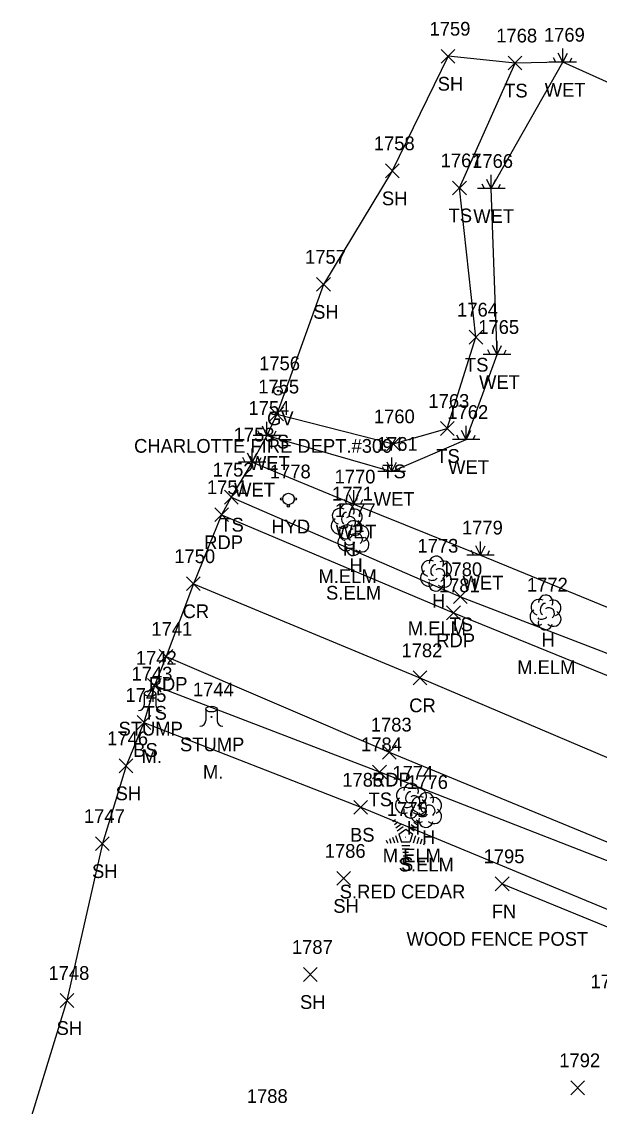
# Model space of a CAD drawing. Extents: x 1459992 to 1461532, y 647785 to 648535.
# Drawn here: x 1460921.8 to 1461005.9, y 648288.6 to 648446.3 of the extents above; entities that cross this region are included whole.
import ezdxf

# ---------------------------------------------------------------- set-up
doc = ezdxf.new("R2010")
doc.units = 0
for name, color, linetype in [('L_A', 7, 'Continuous'), ('L_C', 7, 'Continuous'), ('L_I', 7, 'Continuous'), ('L_TIC', 7, 'Continuous'), ('LELB', 7, 'Continuous'), ('LFNC', 7, 'Continuous'), ('LSOGP', 7, 'Continuous'), ('LTC', 7, 'Continuous'), ('LTD', 7, 'Continuous'), ('LTS', 7, 'Continuous'), ('LWET', 7, 'Continuous'), ('P_A', 7, 'Continuous'), ('P_I', 7, 'Continuous'), ('P_TIC', 7, 'Continuous'), ('PET', 7, 'Continuous'), ('PRC', 7, 'Continuous'), ('U_A', 7, 'Continuous'), ('U_C', 7, 'Continuous'), ('U_I', 7, 'Continuous'), ('UWFH', 7, 'Continuous'), ('UWV', 7, 'Continuous')]:
    doc.layers.add(name, color=color, linetype=linetype)

msp = doc.modelspace()

# ---------------------------------------------------------------- linework, layer by layer
at = {"layer": 'L_TIC'}
for points in [[(1460982.9, 648440.23), (1460984.9, 648442.23)], [(1460984.9, 648440.23), (1460982.9, 648442.23)], [(1460992.65, 648439.24), (1460994.65, 648441.24)], [(1460994.65, 648439.24), (1460992.65, 648441.24)], [(1460974.78, 648423.57), (1460976.78, 648425.57)], [(1460976.78, 648423.57), (1460974.78, 648425.57)], [(1460984.56, 648421.09), (1460986.56, 648423.09)], [(1460986.56, 648421.09), (1460984.56, 648423.09)], [(1460964.77, 648407.07), (1460966.77, 648409.07)], [(1460966.77, 648407.07), (1460964.77, 648409.07)], [(1460986.95, 648399.39), (1460988.95, 648401.39)], [(1460988.95, 648399.39), (1460986.95, 648401.39)], [(1460957.96, 648388.21), (1460959.96, 648390.21)], [(1460959.96, 648388.21), (1460957.96, 648390.21)], [(1460982.78, 648386.12), (1460984.78, 648388.12)], [(1460984.78, 648386.12), (1460982.78, 648388.12)], [(1460974.92, 648383.88), (1460976.92, 648385.88)], [(1460976.92, 648383.88), (1460974.92, 648385.88)], [(1460951.34, 648376.13), (1460953.34, 648378.13)], [(1460953.34, 648376.13), (1460951.34, 648378.13)], [(1460984.69, 648361.66), (1460986.69, 648363.66)], [(1460986.69, 648361.66), (1460984.69, 648363.66)], [(1460940.15, 648348.78), (1460942.15, 648350.78)], [(1460942.15, 648348.78), (1460940.15, 648350.78)], [(1460938.64, 648343.38), (1460940.64, 648345.38)], [(1460940.64, 648343.38), (1460938.64, 648345.38)], [(1460936.03, 648337.08), (1460938.03, 648339.08)], [(1460938.03, 648337.08), (1460936.03, 648339.08)], [(1460972.92, 648336.2), (1460974.92, 648338.2)], [(1460974.92, 648336.2), (1460972.92, 648338.2)], [(1460970.19, 648331.05), (1460972.19, 648333.05)], [(1460972.19, 648331.05), (1460970.19, 648333.05)], [(1460932.59, 648325.77), (1460934.59, 648327.77)], [(1460934.59, 648325.77), (1460932.59, 648327.77)], [(1460967.7, 648320.71), (1460969.7, 648322.71)], [(1460969.7, 648320.71), (1460967.7, 648322.71)], [(1460990.77, 648319.92), (1460992.77, 648321.92)], [(1460992.77, 648319.92), (1460990.77, 648321.92)], [(1460962.86, 648306.74), (1460964.86, 648308.74)], [(1460964.86, 648306.74), (1460962.86, 648308.74)], [(1460927.43, 648302.96), (1460929.43, 648304.96)], [(1460929.43, 648302.96), (1460927.43, 648304.96)], [(1461001.77, 648290.27), (1461003.77, 648292.27)], [(1461003.77, 648290.27), (1461001.77, 648292.27)]]:
    msp.add_lwpolyline(points, dxfattribs=at)
at = {"layer": 'LELB'}
for points in [[(1460952.34, 648377.13), (1460985.69, 648362.66), (1461027.43, 648346.63), (1461054.39, 648335.28), (1461097.58, 648319.81), (1461127.3, 648308.18), (1461153.51, 648301.33), (1461179.78, 648297.83), (1461204.84, 648300.47), (1461233.15, 648308.09), (1461257.01, 648318.59), (1461281.51, 648336.52), (1461300.79, 648352.57), (1461310.07, 648360.68), (1461331.77, 648379.2), (1461352.47, 648399.38), (1461367.35, 648413.21), (1461394.44, 648433.89), (1461417.38, 648445.8)], [(1460958.96, 648389.21), (1460975.92, 648384.88), (1460983.78, 648387.12), (1460987.95, 648400.39), (1460985.56, 648422.09), (1460993.65, 648440.24)], [(1460941.15, 648349.78), (1460973.92, 648337.2), (1461015.24, 648321.11), (1461040.67, 648310.01), (1461064.18, 648298.16), (1461082.22, 648291.36), (1461125.02, 648274.34), (1461150.75, 648265.39), (1461172.28, 648256.95), (1461198.57, 648246.42), (1461223, 648236.28), (1461241.79, 648231.37), (1461257.62, 648226.89), (1461266.9, 648221.63), (1461276.01, 648214.68), (1461281.47, 648211.06), (1461286.34, 648210.46)], [(1460939.64, 648344.38), (1460971.19, 648332.05), (1461013, 648314.77), (1461039.31, 648304.76), (1461062.9, 648294.47), (1461067.87, 648294.36), (1461073.92, 648287.11), (1461122.33, 648270.19), (1461146.57, 648259.51), (1461168.44, 648252.02), (1461196.41, 648241.56), (1461220.18, 648231.28), (1461239.03, 648226.47), (1461251, 648216.36), (1461259.3, 648208.22), (1461262.9, 648204.94)]]:
    msp.add_lwpolyline(points, dxfattribs=at)
at = {"layer": 'LFNC'}
msp.add_lwpolyline([(1460991.77, 648320.92), (1461037.89, 648302.09), (1461026.11, 648281.23)], dxfattribs=at)
at = {"layer": 'LSOGP'}
msp.add_lwpolyline([(1461138.91, 648400.04), (1461102.42, 648405.45), (1461097.92, 648407.66), (1461049.42, 648422.26), (1461028.66, 648427.76), (1461000.6, 648440.35), (1460993.65, 648440.24), (1460983.9, 648441.23), (1460975.78, 648424.57), (1460965.77, 648408.07), (1460958.96, 648389.21), (1460957.54, 648386.1), (1460955.38, 648382.22), (1460952.34, 648377.13), (1460950.93, 648374.58), (1460946.83, 648364.55), (1460942.85, 648353.98), (1460941.15, 648349.78), (1460940.52, 648347.48), (1460939.64, 648344.38), (1460937.03, 648338.08), (1460933.59, 648326.77), (1460928.43, 648303.96), (1460921.84, 648282.44)], dxfattribs=at)
at = {"layer": 'LTC'}
for p, q in [((1460975.87, 648330.01), (1460976.23, 648330.27)), ((1460976.08, 648329.55), (1460976.61, 648329.93)), ((1460976.29, 648329.08), (1460977, 648329.59)), ((1460978.53, 648329.55), (1460979.21, 648329.06)), ((1460978.9, 648329.9), (1460979.45, 648329.5)), ((1460979.27, 648330.25), (1460979.69, 648329.95)), ((1460976.27, 648327.94), (1460976.6, 648326.92)), ((1460976.5, 648328.61), (1460977.38, 648329.25)), ((1460976.73, 648328.16), (1460977.74, 648328.89)), ((1460976.73, 648328.16), (1460977.11, 648326.97)), ((1460977.74, 648328.89), (1460978.74, 648328.17)), ((1460978.16, 648329.21), (1460978.97, 648328.62)), ((1460978.74, 648328.17), (1460978.34, 648326.97)), ((1460979.17, 648327.9), (1460978.84, 648326.86)), ((1460974.91, 648327.29), (1460975.06, 648326.82)), ((1460975.36, 648327.51), (1460975.57, 648326.85)), ((1460975.82, 648327.72), (1460976.09, 648326.89)), ((1460978.34, 648326.97), (1460977.11, 648326.97)), ((1460978.31, 648326.47), (1460977.16, 648326.47)), ((1460979.62, 648327.65), (1460979.33, 648326.76)), ((1460980.06, 648327.4), (1460979.83, 648326.67)), ((1460980.51, 648327.15), (1460980.32, 648326.57)), ((1460978.22, 648325.97), (1460977.23, 648325.97)), ((1460978.14, 648325.47), (1460977.31, 648325.47)), ((1460978.05, 648324.97), (1460977.38, 648324.97))]:
    msp.add_line(p, q, dxfattribs=at)
at = {"layer": 'LTD'}
for p, q in [((1460969.13, 648373.65), (1460969.13, 648373.65)), ((1460969.13, 648373.65), (1460969.13, 648373.65)), ((1460970.11, 648371.24), (1460970.11, 648371.24)), ((1460970.11, 648371.24), (1460970.11, 648371.24)), ((1460982.13, 648366.07), (1460982.13, 648366.07)), ((1460982.13, 648366.07), (1460982.13, 648366.07)), ((1460998.06, 648360.42), (1460998.06, 648360.42)), ((1460998.06, 648360.42), (1460998.06, 648360.42)), ((1460978.48, 648333.06), (1460978.48, 648333.06)), ((1460978.48, 648333.06), (1460978.48, 648333.06)), ((1460980.68, 648331.72), (1460980.68, 648331.72)), ((1460980.68, 648331.72), (1460980.68, 648331.72))]:
    msp.add_line(p, q, dxfattribs=at)
for centre in [(1460969.18, 648375.08), (1460970.15, 648372.67), (1460982.18, 648367.51), (1460998.11, 648361.85), (1460978.53, 648334.49), (1460980.72, 648333.15)]:
    msp.add_arc(centre, 1.05, 335.5272, 180.9563, dxfattribs=at)
for centre, major_axis, ratio, start_param, end_param in [((1460968.34, 648374.32), (1.21, -0.51), 0.895232, 1.570796, 4.712389), ((1460970.18, 648374.23), (-1.14, -0.48), 0.949671, 1.570796, 4.712389), ((1460968.05, 648372.94), (0.58, -1.04), 0.959034, 3.141593, 6.283185), ((1460968.93, 648374.11), (-0.208, -0.792), 0.645439, 3.141593, 6.283185), ((1460969.63, 648373.48), (-0.5, 0.667), 0.989748, 3.141593, 6.283185), ((1460970.13, 648372.82), (-1.09, 0.79), 0.841452, 1.570796, 4.712389), ((1460969.31, 648371.9), (1.21, -0.51), 0.895232, 1.570796, 4.712389), ((1460969.13, 648372.15), (0.26, 1.06), 0.942809, 1.570796, 4.712389), ((1460968.68, 648372.9), (-0.625, -0.083), 0.423636, 0, 3.141593), ((1460969.9, 648371.69), (-0.208, -0.792), 0.645439, 3.141593, 6.283185), ((1460970.61, 648371.07), (-0.5, 0.667), 0.989748, 3.141593, 6.283185), ((1460971.15, 648371.82), (-1.14, -0.48), 0.949671, 1.570796, 4.712389), ((1460969.02, 648370.53), (0.58, -1.04), 0.959034, 3.141593, 6.283185), ((1460969.65, 648370.49), (-0.625, -0.083), 0.423636, 0, 3.141593), ((1460971.11, 648370.4), (-1.09, 0.79), 0.841452, 1.570796, 4.712389), ((1460970.11, 648369.74), (0.26, 1.06), 0.942809, 1.570796, 4.712389), ((1460981.34, 648366.74), (1.21, -0.51), 0.895232, 1.570796, 4.712389), ((1460981.92, 648366.53), (-0.208, -0.792), 0.645439, 3.141593, 6.283185), ((1460983.17, 648366.66), (-1.14, -0.48), 0.949671, 1.570796, 4.712389), ((1460981.05, 648365.37), (0.58, -1.04), 0.959034, 3.141593, 6.283185), ((1460982.63, 648365.91), (-0.5, 0.667), 0.989748, 3.141593, 6.283185), ((1460983.13, 648365.24), (-1.09, 0.79), 0.841452, 1.570796, 4.712389), ((1460982.13, 648364.57), (0.26, 1.06), 0.942809, 1.570796, 4.712389), ((1460981.67, 648365.32), (-0.625, -0.083), 0.423636, 0, 3.141593), ((1460997.27, 648361.09), (1.21, -0.51), 0.895232, 1.570796, 4.712389), ((1460997.85, 648360.88), (-0.208, -0.792), 0.645439, 3.141593, 6.283185), ((1460998.56, 648360.25), (-0.5, 0.667), 0.989748, 3.141593, 6.283185), ((1460999.1, 648361), (-1.14, -0.48), 0.949671, 1.570796, 4.712389), ((1460996.98, 648359.71), (0.58, -1.04), 0.959034, 3.141593, 6.283185), ((1460997.6, 648359.67), (-0.625, -0.083), 0.423636, 0, 3.141593), ((1460999.06, 648359.59), (-1.09, 0.79), 0.841452, 1.570796, 4.712389), ((1460998.06, 648358.92), (0.26, 1.06), 0.942809, 1.570796, 4.712389), ((1460977.69, 648333.73), (1.21, -0.51), 0.895232, 1.570796, 4.712389), ((1460978.27, 648333.52), (-0.208, -0.792), 0.645439, 3.141593, 6.283185), ((1460979.52, 648333.64), (-1.14, -0.48), 0.949671, 1.570796, 4.712389), ((1460977.4, 648332.35), (0.58, -1.04), 0.959034, 3.141593, 6.283185), ((1460979.89, 648332.38), (1.21, -0.51), 0.895232, 1.570796, 4.712389), ((1460978.98, 648332.89), (-0.5, 0.667), 0.989748, 3.141593, 6.283185), ((1460979.48, 648332.23), (-1.09, 0.79), 0.841452, 1.570796, 4.712389), ((1460980.47, 648332.17), (-0.208, -0.792), 0.645439, 3.141593, 6.283185), ((1460981.72, 648332.3), (-1.14, -0.48), 0.949671, 1.570796, 4.712389), ((1460978.48, 648331.56), (0.26, 1.06), 0.942809, 1.570796, 4.712389), ((1460978.02, 648332.31), (-0.625, -0.083), 0.423636, 0, 3.141593), ((1460979.59, 648331.01), (0.58, -1.04), 0.959034, 3.141593, 6.283185), ((1460980.22, 648330.97), (-0.625, -0.083), 0.423636, 0, 3.141593), ((1460981.18, 648331.55), (-0.5, 0.667), 0.989748, 3.141593, 6.283185), ((1460981.68, 648330.88), (-1.09, 0.79), 0.841452, 1.570796, 4.712389), ((1460980.68, 648330.22), (0.26, 1.06), 0.942809, 1.570796, 4.712389)]:
    msp.add_ellipse(centre, major_axis=major_axis, ratio=ratio, start_param=start_param, end_param=end_param, dxfattribs=at)
at = {"layer": 'LTS'}
for p, q in [((1460939.69, 648348.61), (1460939.69, 648346.95)), ((1460941.36, 648348.45), (1460941.36, 648348.61)), ((1460941.36, 648348.61), (1460941.36, 648346.95)), ((1460940.52, 648347.47), (1460940.52, 648347.47)), ((1460940.52, 648347.47), (1460940.52, 648347.47)), ((1460940.52, 648347.45), (1460940.52, 648347.45)), ((1460948.62, 648346.33), (1460948.62, 648344.66)), ((1460950.29, 648346.16), (1460950.29, 648346.33)), ((1460950.29, 648346.33), (1460950.29, 648344.66)), ((1460949.46, 648345.19), (1460949.46, 648345.19)), ((1460949.46, 648345.19), (1460949.46, 648345.19)), ((1460949.46, 648345.16), (1460949.46, 648345.16))]:
    msp.add_line(p, q, dxfattribs=at)
for centre in [(1460940.52, 648347.47), (1460949.46, 648345.19)]:
    msp.add_circle(centre, 0.0833, dxfattribs=at)
for centre, start, end in [((1460938.86, 648346.95), 270, 360), ((1460942.19, 648346.95), 180, 270), ((1460947.79, 648344.66), 270, 360), ((1460951.12, 648344.66), 180, 270)]:
    msp.add_arc(centre, 0.833, start, end, dxfattribs=at)
for centre in [(1460940.52, 648348.61), (1460949.46, 648346.33)]:
    msp.add_ellipse(centre, major_axis=(-0.833, 0), ratio=0.5, dxfattribs=at)
at = {"layer": 'LWET'}
for p, q in [((1461000.6, 648440.35), (1460999.93, 648441.69)), ((1461000.6, 648440.35), (1461000.6, 648442.35)), ((1461000.6, 648440.35), (1461001.26, 648441.69)), ((1461002.6, 648440.35), (1460998.6, 648440.35)), ((1460999.6, 648440.35), (1460999.26, 648441.02)), ((1461001.6, 648440.35), (1461001.93, 648441.02)), ((1460989.19, 648422), (1460988.86, 648422.66)), ((1460990.19, 648422), (1460989.52, 648423.33)), ((1460990.19, 648422), (1460990.19, 648424)), ((1460990.19, 648422), (1460990.86, 648423.33)), ((1460991.19, 648422), (1460991.52, 648422.66)), ((1460992.19, 648422), (1460988.19, 648422)), ((1460991.03, 648397.87), (1460990.36, 648399.2)), ((1460991.03, 648397.87), (1460991.03, 648399.87)), ((1460991.03, 648397.87), (1460991.69, 648399.2)), ((1460993.03, 648397.87), (1460989.03, 648397.87)), ((1460990.03, 648397.87), (1460989.69, 648398.53)), ((1460992.03, 648397.87), (1460992.36, 648398.53)), ((1460957.54, 648386.1), (1460957.54, 648388.1)), ((1460956.54, 648386.1), (1460956.21, 648386.77)), ((1460957.54, 648386.1), (1460956.88, 648387.44)), ((1460957.54, 648386.1), (1460958.21, 648387.44)), ((1460958.54, 648386.1), (1460958.88, 648386.77)), ((1460986.53, 648385.51), (1460985.86, 648386.84)), ((1460986.53, 648385.51), (1460986.53, 648387.51)), ((1460986.53, 648385.51), (1460987.19, 648386.84)), ((1460959.54, 648386.1), (1460955.54, 648386.1)), ((1460988.53, 648385.51), (1460984.53, 648385.51)), ((1460985.53, 648385.51), (1460985.19, 648386.17)), ((1460987.53, 648385.51), (1460987.86, 648386.17)), ((1460955.38, 648382.22), (1460954.72, 648383.55)), ((1460955.38, 648382.22), (1460955.38, 648384.22)), ((1460955.38, 648382.22), (1460956.05, 648383.55)), ((1460957.38, 648382.22), (1460953.38, 648382.22)), ((1460954.38, 648382.22), (1460954.05, 648382.88)), ((1460956.38, 648382.22), (1460956.72, 648382.88)), ((1460974.7, 648380.88), (1460974.37, 648381.55)), ((1460975.7, 648380.88), (1460975.04, 648382.22)), ((1460975.7, 648380.88), (1460975.7, 648382.88)), ((1460975.7, 648380.88), (1460976.37, 648382.22)), ((1460976.7, 648380.88), (1460977.04, 648381.55)), ((1460977.7, 648380.88), (1460973.7, 648380.88)), ((1460969.16, 648376.13), (1460968.83, 648376.8)), ((1460970.16, 648376.13), (1460969.49, 648377.46)), ((1460970.16, 648376.13), (1460970.16, 648378.13)), ((1460970.16, 648376.13), (1460970.83, 648377.46)), ((1460971.16, 648376.13), (1460971.49, 648376.8)), ((1460972.16, 648376.13), (1460968.16, 648376.13)), ((1460988.62, 648368.71), (1460988.62, 648370.71)), ((1460987.62, 648368.71), (1460987.29, 648369.38)), ((1460988.62, 648368.71), (1460987.95, 648370.04)), ((1460988.62, 648368.71), (1460989.29, 648370.04)), ((1460989.62, 648368.71), (1460989.95, 648369.38)), ((1460990.62, 648368.71), (1460986.62, 648368.71))]:
    msp.add_line(p, q, dxfattribs=at)
for points in [[(1460957.54, 648386.1), (1460975.7, 648380.88), (1460986.53, 648385.51), (1460991.03, 648397.87), (1460990.19, 648422), (1461000.6, 648440.35)], [(1460955.38, 648382.22), (1460970.16, 648376.13), (1460988.62, 648368.71), (1461029.04, 648352.15), (1461045.75, 648345.16), (1461061.43, 648365.6), (1461078.4, 648387.06), (1461097.92, 648407.66)]]:
    msp.add_lwpolyline(points, dxfattribs=at)
at = {"layer": 'P_TIC'}
for points in [[(1460949.93, 648373.58), (1460951.93, 648375.58)], [(1460951.93, 648373.58), (1460949.93, 648375.58)], [(1460945.83, 648363.55), (1460947.83, 648365.55)], [(1460947.83, 648363.55), (1460945.83, 648365.55)], [(1460983.69, 648359.32), (1460985.69, 648361.32)], [(1460985.69, 648359.32), (1460983.69, 648361.32)], [(1460941.85, 648352.98), (1460943.85, 648354.98)], [(1460943.85, 648352.98), (1460941.85, 648354.98)], [(1460978.81, 648349.87), (1460980.81, 648351.87)], [(1460980.81, 648349.87), (1460978.81, 648351.87)], [(1460974.34, 648339.07), (1460976.34, 648341.07)], [(1460976.34, 648339.07), (1460974.34, 648341.07)]]:
    msp.add_lwpolyline(points, dxfattribs=at)
at = {"layer": 'PET'}
for points in [[(1460950.93, 648374.58), (1460984.69, 648360.32), (1461025.42, 648343.73), (1461053.38, 648332.51), (1461095.05, 648316.17), (1461126.17, 648304.95), (1461152.62, 648298.48), (1461179.86, 648295.54), (1461205.35, 648297.28), (1461234.43, 648304.94), (1461258.07, 648315.7), (1461283.68, 648333.5), (1461302.87, 648349.75), (1461333.02, 648377.55), (1461355.02, 648397.13), (1461371.06, 648410.57), (1461396.62, 648429.43), (1461418.97, 648443.38)], [(1460942.85, 648353.98), (1460975.34, 648340.07), (1461016.08, 648323.29), (1461041.44, 648312.66), (1461070.03, 648301.09), (1461083.95, 648295.62), (1461128.85, 648279.26), (1461164.21, 648269.58), (1461178.63, 648262.65), (1461203.09, 648251.99), (1461227.86, 648243.02), (1461244.86, 648238.13), (1461258.8, 648233.38), (1461270.23, 648226.19), (1461279.65, 648219.62), (1461287.61, 648211.81)]]:
    msp.add_lwpolyline(points, dxfattribs=at)
at = {"layer": 'PRC'}
msp.add_lwpolyline([(1460946.83, 648364.55), (1460979.81, 648350.87), (1461020.89, 648333.41), (1461048.05, 648322.3), (1461089.53, 648305.67), (1461120.42, 648294.12), (1461149.17, 648286), (1461180.56, 648282.29), (1461207.18, 648283.7), (1461238.84, 648291.79), (1461263.78, 648303.51), (1461290.77, 648322.92), (1461310.31, 648340.94), (1461342.22, 648370.37), (1461365.17, 648390.4), (1461371.57, 648396.04), (1461402.62, 648419.98), (1461424.86, 648433.53)], dxfattribs=at)
at = {"layer": 'UWFH'}
msp.add_line((1460960.66, 648376.87), (1460960.66, 648376.87), dxfattribs=at)
for centre, radius in [((1460959.66, 648376.87), 0.167), ((1460960.66, 648376.87), 0.833), ((1460961.66, 648376.87), 0.167), ((1460960.66, 648375.87), 0.167)]:
    msp.add_circle(centre, radius, dxfattribs=at)
at = {"layer": 'UWV'}
for radius in [0.625, 0.0833]:
    msp.add_circle((1460959.15, 648392.59), radius, dxfattribs=at)

# ---------------------------------------------------------------- texts
at = {"layer": 'L_A'}
for s, p in [('SH', (1460982.39, 648436.23)), ('TS', (1460992.06, 648435.24)), ('WET', (1460997.97, 648435.35)), ('SH', (1460974.27, 648419.57)), ('TS', (1460983.97, 648417.09)), ('WET', (1460987.57, 648417)), ('SH', (1460964.26, 648403.07)), ('TS', (1460986.36, 648395.39)), ('WET', (1460988.41, 648392.87)), ('TS', (1460957.37, 648384.21)), ('WET', (1460954.92, 648381.1)), ('TS', (1460982.19, 648382.12)), ('TS', (1460974.33, 648379.88)), ('WET', (1460983.91, 648380.51)), ('WET', (1460952.76, 648377.22)), ('WET', (1460973.08, 648375.88)), ('TS', (1460950.75, 648372.13)), ('WET', (1460967.54, 648371.13)), ('H', (1460968.57, 648368.65)), ('H', (1460969.54, 648366.24)), ('WET', (1460986, 648363.71)), ('H', (1460981.56, 648361.07)), ('TS', (1460984.1, 648357.66)), ('H', (1460997.49, 648355.42)), ('TS', (1460939.56, 648344.78)), ('STUMP', (1460935.94, 648342.48)), ('STUMP', (1460944.88, 648340.19)), ('BS', (1460938.08, 648339.38)), ('SH', (1460935.52, 648333.08)), ('TS', (1460972.33, 648332.2)), ('H', (1460977.91, 648328.06)), ('BS', (1460969.63, 648327.05)), ('H', (1460980.11, 648326.72)), ('S', (1460977.06, 648322.8)), ('SH', (1460932.08, 648321.77)), ('SH', (1460967.19, 648316.71)), ('FN', (1460990.25, 648315.92)), ('SH', (1460962.35, 648302.74)), ('SH', (1460926.92, 648298.96))]:
    msp.add_text(s, height=2, dxfattribs=at).set_placement(p)
at = {"layer": 'L_C'}
for s, p in [('M.ELM', (1460965.04, 648364.65)), ('S.ELM', (1460966.14, 648362.24)), ('M.ELM', (1460978.03, 648357.07)), ('M.ELM', (1460993.96, 648351.42)), ('M.', (1460939.29, 648338.48)), ('M.', (1460948.22, 648336.19)), ('M.ELM', (1460974.39, 648324.06)), ('S.ELM', (1460976.71, 648322.72)), ('S.RED CEDAR', (1460968.13, 648318.8)), ('WOOD FENCE POST', (1460977.85, 648311.92))]:
    msp.add_text(s, height=2, dxfattribs=at).set_placement(p)
at = {"layer": 'L_I'}
for s, p in [('1759', (1460981.2, 648444.23)), ('1768', (1460990.91, 648443.24)), ('1769', (1460997.85, 648443.35)), ('1758', (1460973.09, 648427.57)), ('1767', (1460982.82, 648425.09)), ('1766', (1460987.4, 648425)), ('1757', (1460963.08, 648411.07)), ('1764', (1460985.21, 648403.39)), ('1765', (1460988.29, 648400.87)), ('1755', (1460956.27, 648392.21)), ('1754', (1460954.85, 648389.1)), ('1763', (1460981.04, 648390.12)), ('1760', (1460973.1, 648387.88)), ('1762', (1460983.79, 648388.51)), ('1753', (1460952.69, 648385.22)), ('1761', (1460973.53, 648383.88)), ('1752', (1460949.64, 648380.13)), ('1770', (1460967.38, 648379.13)), ('1771', (1460967.01, 648376.65)), ('1777', (1460967.41, 648374.24)), ('1779', (1460985.92, 648371.71)), ('1773', (1460979.44, 648369.07)), ('1780', (1460982.91, 648365.66)), ('1772', (1460995.37, 648363.42)), ('1742', (1460938.46, 648352.78)), ('1743', (1460937.83, 648350.48)), ('1744', (1460946.76, 648348.19)), ('1745', (1460936.95, 648347.38)), ('1746', (1460934.28, 648341.08)), ('1784', (1460971.23, 648340.2)), ('1774', (1460975.79, 648336.06)), ('1785', (1460968.5, 648335.05)), ('1776', (1460977.93, 648334.72)), ('1775', (1460974.99, 648330.8)), ('1747', (1460930.9, 648329.77)), ('1786', (1460965.95, 648324.71)), ('1795', (1460989.07, 648323.92)), ('1787', (1460961.17, 648310.74)), ('1748', (1460925.74, 648306.96)), ('1793', (1461004.63, 648305.74)), ('1792', (1461000.08, 648294.27)), ('1788', (1460954.61, 648289.07))]:
    msp.add_text(s, height=2, dxfattribs=at).set_placement(p)
at = {"layer": 'LTC'}
msp.add_text('.', height=1.04, rotation=270, dxfattribs=at).set_placement((1460977.62, 648327.91))
at = {"layer": 'P_A'}
for s, p in [('RDP', (1460948.41, 648369.58)), ('CR', (1460945.26, 648359.55)), ('RDP', (1460982.18, 648355.32)), ('RDP', (1460940.33, 648348.98)), ('CR', (1460978.24, 648345.87)), ('RDP', (1460972.83, 648335.07))]:
    msp.add_text(s, height=2, dxfattribs=at).set_placement(p)
at = {"layer": 'P_I'}
for s, p in [('1751', (1460948.8, 648377.58)), ('1750', (1460944.05, 648367.55)), ('1781', (1460982.56, 648363.32)), ('1741', (1460940.72, 648356.98)), ('1782', (1460977.12, 648353.87)), ('1783', (1460972.65, 648343.07))]:
    msp.add_text(s, height=2, dxfattribs=at).set_placement(p)
at = {"layer": 'U_A'}
for s, p in [('GV', (1460957.55, 648387.59)), ('HYD', (1460958.18, 648371.87))]:
    msp.add_text(s, height=2, dxfattribs=at).set_placement(p)
at = {"layer": 'U_C'}
msp.add_text('CHARLOTTE FIRE DEPT.#309', height=2, dxfattribs=at).set_placement((1460938.2, 648383.59))
at = {"layer": 'U_I'}
for s, p in [('1756', (1460956.4, 648395.59)), ('1778', (1460957.96, 648379.87))]:
    msp.add_text(s, height=2, dxfattribs=at).set_placement(p)

doc.saveas('drawing.dxf')
